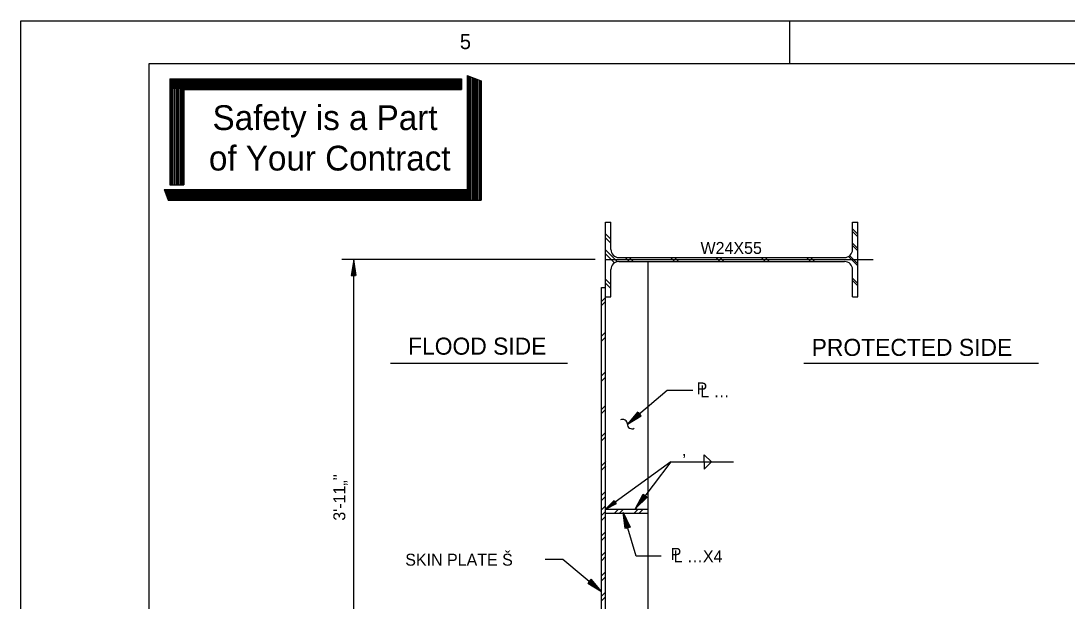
# Model space of a CAD drawing. Extents: x 4.9 to 31.6, y 3.9 to 22.6.
# Drawn here: x 4.91 to 13.07, y 18.06 to 22.59 of the extents above; entities that cross this region are included whole.
import ezdxf

# ---------------------------------------------------------------- set-up
doc = ezdxf.new("R2010")
doc.units = 0
for name, color, linetype in [('Level 1', 7, 'Continuous'), ('Level 10', 7, 'Continuous'), ('Level 2', 7, 'Continuous'), ('Level 25', 7, 'Continuous'), ('Level 3', 7, 'Continuous'), ('Level 44', 7, 'Continuous'), ('Level 50', 7, 'Continuous')]:
    doc.layers.add(name, color=color, linetype=linetype)

msp = doc.modelspace()

# ---------------------------------------------------------------- linework, layer by layer
at = {"layer": 'Level 1'}
for p, q in [((10.9069, 22.2594), (10.9069, 22.5927)), ((6.0674, 22.1412), (8.3454, 22.1412)), ((6.0674, 22.1412), (6.0674, 21.3139)), ((6.0674, 22.1306), (8.3454, 22.1306)), ((6.0674, 22.1206), (8.3454, 22.1206)), ((6.0781, 22.1412), (6.0781, 21.3139)), ((6.0881, 22.1412), (6.0881, 21.3139)), ((6.0988, 22.1412), (6.0988, 21.3139)), ((6.1088, 22.1412), (6.1088, 21.3139)), ((6.1194, 22.1412), (6.1194, 21.3139)), ((6.1301, 22.1412), (6.1301, 21.3139)), ((6.1401, 22.1412), (6.1401, 21.3139)), ((6.1508, 22.1412), (6.1508, 21.3139)), ((6.1614, 22.1412), (6.1614, 21.3139)), ((6.1714, 22.1412), (6.1714, 21.3139)), ((8.3454, 22.1412), (8.3454, 22.0579)), ((8.3874, 22.1659), (8.3874, 21.2766)), ((8.3874, 22.1659), (8.4988, 22.1246)), ((8.3948, 22.1632), (8.3948, 21.1932)), ((8.4048, 22.1592), (8.4048, 21.1932)), ((8.4154, 22.1552), (8.4154, 21.1932)), ((8.4261, 22.1512), (8.4261, 21.1932)), ((8.4361, 22.1479), (8.4361, 21.1932)), ((8.4468, 22.1439), (8.4468, 21.1932)), ((8.4568, 22.1399), (8.4568, 21.1932)), ((8.4674, 22.1359), (8.4674, 21.1932)), ((8.4781, 22.1326), (8.4781, 21.1932)), ((8.4881, 22.1246), (8.4881, 21.1932)), ((8.4988, 22.1246), (8.4988, 21.1932)), ((6.0674, 22.1099), (8.3454, 22.1099)), ((6.0674, 22.0992), (8.3454, 22.0992)), ((6.0674, 22.0892), (8.3454, 22.0892)), ((6.0674, 22.0786), (8.3454, 22.0786)), ((6.0674, 22.0686), (8.3454, 22.0686)), ((6.1788, 22.0579), (8.3454, 22.0579)), ((6.1788, 22.0579), (6.1788, 21.3139)), ((6.0674, 21.3139), (6.1788, 21.3139)), ((6.0254, 21.2766), (8.3874, 21.2766)), ((6.0254, 21.2766), (6.0561, 21.1932)), ((6.0294, 21.2659), (8.3948, 21.2659)), ((6.0328, 21.2559), (8.3948, 21.2559)), ((6.0368, 21.2452), (8.3948, 21.2452)), ((6.0408, 21.2346), (8.3948, 21.2346)), ((6.0448, 21.2246), (8.3948, 21.2246)), ((6.0488, 21.2139), (8.3948, 21.2139)), ((6.0521, 21.2039), (8.3948, 21.2039)), ((6.0561, 21.1932), (8.4988, 21.1932))]:
    msp.add_line(p, q, dxfattribs=at)
for points in [[(4.9069, 22.5927), (31.5735, 22.5927), (31.5735, 3.926), (4.9069, 3.926)], [(5.9069, 22.2594), (31.2402, 22.2594), (31.2402, 4.2594), (5.9069, 4.2594)]]:
    msp.add_lwpolyline(points, close=True, dxfattribs=at)
at = {"layer": 'Level 10'}
for p, q in [((9.4366, 20.4023), (9.4679, 20.4335)), ((9.4366, 20.3708), (9.4679, 20.402)), ((9.4366, 20.131), (9.4679, 20.1622)), ((9.4366, 20.0934), (9.4679, 20.1246)), ((9.4366, 19.8209), (9.4679, 19.8521)), ((9.4366, 19.781), (9.4679, 19.8122)), ((9.4366, 19.5606), (9.4679, 19.5918)), ((9.4366, 19.5279), (9.4679, 19.5591)), ((9.4353, 19.3159), (9.4666, 19.3472)), ((9.4366, 19.3486), (9.4679, 19.3799)), ((9.4379, 19.1234), (9.4692, 19.1546)), ((9.4379, 19.0895), (9.4692, 19.1207)), ((9.4366, 18.8873), (9.4679, 18.9185)), ((9.4366, 18.8496), (9.4679, 18.8808)), ((9.4366, 18.7754), (9.4679, 18.8067)), ((9.537, 18.7509), (9.5682, 18.7821)), ((9.5764, 18.7509), (9.6077, 18.7821)), ((9.6907, 18.7509), (9.7219, 18.7821)), ((9.7301, 18.7509), (9.7614, 18.7821)), ((9.4366, 18.7317), (9.4679, 18.7629)), ((9.4366, 18.6922), (9.4679, 18.7235)), ((9.4366, 18.6922), (9.4679, 18.7235)), ((9.4366, 18.5744), (9.4679, 18.6056)), ((9.4366, 18.5367), (9.4679, 18.5679)), ((9.4366, 18.4171), (9.4679, 18.4483)), ((9.4366, 18.3793), (9.4679, 18.4106)), ((9.4366, 18.2597), (9.4679, 18.291)), ((9.4366, 18.222), (9.4679, 18.2533)), ((9.4366, 18.1024), (9.4679, 18.1337)), ((9.4366, 18.0647), (9.4679, 18.0959))]:
    msp.add_line(p, q, dxfattribs=at)
at = {"layer": 'Level 2'}
for p, q in [((9.4679, 20.4384), (9.4679, 21.0217)), ((9.4679, 21.0217), (9.5095, 21.0217)), ((9.5095, 20.8082), (9.5095, 21.0217)), ((11.3949, 20.8082), (11.3949, 21.0217)), ((11.3949, 21.0217), (11.4366, 21.0217)), ((11.4366, 20.4384), (11.4366, 21.0217)), ((11.4366, 20.9272), (11.3949, 20.9688)), ((11.4366, 20.9083), (11.3949, 20.95)), ((11.4366, 20.8173), (11.3949, 20.8589)), ((11.4366, 20.7984), (11.3949, 20.8401)), ((9.572, 20.7457), (11.3324, 20.7457)), ((11.4366, 20.6806), (11.3672, 20.75)), ((9.4679, 20.73), (11.5564, 20.73)), ((9.5095, 20.4384), (9.5095, 20.6519)), ((9.572, 20.7144), (11.3324, 20.7144)), ((9.8012, 16.8271), (9.8012, 20.7144)), ((10.3429, 20.7144), (10.6762, 20.7144)), ((11.3949, 20.4384), (11.3949, 20.6519)), ((11.4366, 20.5438), (11.3949, 20.5855)), ((9.4366, 20.5113), (9.4679, 20.5113)), ((9.4366, 16.8271), (9.4366, 20.5113)), ((9.4679, 20.48), (9.4679, 20.5113)), ((9.4679, 16.8271), (9.4679, 20.5113)), ((11.4366, 20.525), (11.3949, 20.5667)), ((9.4679, 20.4384), (9.5095, 20.4384)), ((11.3949, 20.4384), (11.4366, 20.4384)), ((9.4679, 18.7509), (9.4679, 18.7821)), ((9.8012, 18.7509), (9.8012, 18.7821))]:
    msp.add_line(p, q, dxfattribs=at)
at = {"layer": 'Level 25'}
for p, q in [((9.5095, 20.8878), (9.4679, 20.9295)), ((9.5095, 20.8565), (9.4679, 20.8981)), ((9.5604, 20.7133), (9.4659, 20.8078)), ((9.538, 20.7044), (9.4659, 20.7765)), ((9.6516, 20.7144), (9.6203, 20.7457)), ((9.683, 20.7144), (9.6517, 20.7457)), ((10.0051, 20.7144), (9.9739, 20.7457)), ((10.0365, 20.7144), (10.0053, 20.7457)), ((10.3587, 20.7144), (10.3274, 20.7457)), ((10.3901, 20.7144), (10.3588, 20.7457)), ((10.7123, 20.7144), (10.681, 20.7457)), ((10.7436, 20.7144), (10.7124, 20.7457)), ((11.0658, 20.7144), (11.0346, 20.7457)), ((11.0972, 20.7144), (11.0659, 20.7457)), ((11.4366, 20.6972), (11.374, 20.7597)), ((7.503, 16.803), (7.503, 20.73)), ((9.5095, 20.5343), (9.4679, 20.576)), ((9.5095, 20.5029), (9.4679, 20.5446)), ((9.1716, 19.9197), (7.7908, 19.9197)), ((12.8447, 19.9197), (11.0146, 19.9197)), ((10.2386, 19.2061), (10.2945, 19.1502)), ((10.2386, 19.1498), (10.2386, 19.2061)), ((9.9777, 19.1504), (9.4679, 18.7821)), ((9.9777, 19.1504), (10.4673, 19.1504)), ((10.2386, 19.151), (10.2386, 19.0948)), ((10.2386, 19.0948), (10.2945, 19.1506)), ((9.4679, 18.7821), (9.4679, 18.7821)), ((9.4889, 18.7974), (9.4889, 18.7974))]:
    msp.add_line(p, q, dxfattribs=at)
msp.add_lwpolyline([(9.5346, 18.8494), (9.4679, 18.7821), (9.5527, 18.8243), (9.5372, 18.8458), (9.4889, 18.7974), (9.5466, 18.826), (9.5366, 18.8398), (9.5092, 18.812), (9.5404, 18.8277), (9.5363, 18.8334), (9.5303, 18.8272)], dxfattribs=at)
for centre, start, end in [((9.572, 20.8082), 180, 270), ((11.3324, 20.8082), 270, 0), ((9.572, 20.6519), 90, 180), ((11.3324, 20.6519), 0, 90)]:
    msp.add_arc(centre, 0.0625, start, end, dxfattribs=at)
at = {"layer": 'Level 3'}
for p, q in [((10.4866, 20.7297), (10.4866, 20.7297)), ((10.5743, 20.7136), (10.5743, 20.7136)), ((9.9777, 19.1504), (9.7017, 18.7875))]:
    msp.add_line(p, q, dxfattribs=at)
for points in [[(10.5747, 20.7144), (10.5743, 20.7136)], [(10.5746, 20.7144), (10.5743, 20.7136), (10.5749, 20.7144)], [(10.1495, 19.7071), (9.9488, 19.7071), (9.638, 19.4453)], [(9.9018, 18.4156), (9.7058, 18.4156), (9.6058, 18.7552)], [(8.9967, 18.392), (9.1355, 18.392), (9.4376, 18.1395)]]:
    msp.add_lwpolyline(points, dxfattribs=at)
at = {"layer": 'Level 44'}
for p, q in [((9.4679, 18.7821), (9.8012, 18.7821)), ((9.4679, 18.7509), (9.8012, 18.7509))]:
    msp.add_line(p, q, dxfattribs=at)
for centre, start, end in [((9.6012, 19.4456), 359.59813, 117.47734), ((9.6748, 19.4451), 179.59813, 297.47734)]:
    msp.add_arc(centre, 0.0368, start, end, dxfattribs=at)
at = {"layer": 'Level 50'}
for p, q in [((9.3868, 20.73), (7.4105, 20.73)), ((7.503, 20.73), (7.503, 20.73)), ((7.503, 20.6954), (7.503, 20.6954)), ((9.638, 19.4453), (9.638, 19.4453)), ((9.6645, 19.4676), (9.6645, 19.4676)), ((9.7017, 18.7875), (9.7017, 18.7875)), ((9.7227, 18.8151), (9.7227, 18.8151)), ((9.6058, 18.7552), (9.6058, 18.7552)), ((9.6156, 18.7219), (9.6156, 18.7219)), ((9.411, 18.1617), (9.411, 18.1617)), ((9.4376, 18.1395), (9.4376, 18.1395))]:
    msp.add_line(p, q, dxfattribs=at)
for points in [[(7.5236, 20.6054), (7.503, 20.73), (7.4823, 20.6054), (7.5176, 20.6054), (7.503, 20.6954), (7.489, 20.6107), (7.5116, 20.6107), (7.503, 20.662), (7.4956, 20.616), (7.505, 20.616), (7.503, 20.6274)], [(9.72, 19.5414), (9.638, 19.4453), (9.7467, 19.5098), (9.7239, 19.5368), (9.6645, 19.4676), (9.7383, 19.5115), (9.7237, 19.5288), (9.69, 19.4891), (9.7299, 19.5131), (9.7239, 19.5203), (9.7165, 19.5114)], [(9.7936, 18.8742), (9.7017, 18.7875), (9.7607, 18.8993), (9.7888, 18.8779), (9.7227, 18.8151), (9.7628, 18.891), (9.7808, 18.8773), (9.7428, 18.8416), (9.7648, 18.8827), (9.7723, 18.8771), (9.7638, 18.8692)], [(9.6212, 18.6298), (9.6058, 18.7552), (9.6609, 18.6414), (9.627, 18.6315), (9.6156, 18.7219), (9.6529, 18.6447), (9.6312, 18.6383), (9.625, 18.69), (9.645, 18.6479), (9.6361, 18.6453), (9.6348, 18.6567)], [(9.3287, 18.2036), (9.4376, 18.1395), (9.3552, 18.2353), (9.3326, 18.2082), (9.411, 18.1617), (9.355, 18.2267), (9.3405, 18.2094), (9.3854, 18.1831), (9.3548, 18.2182), (9.3489, 18.211), (9.3588, 18.2053)]]:
    msp.add_lwpolyline(points, dxfattribs=at)

# ---------------------------------------------------------------- texts
at = {"layer": 'Level 1'}
for s, height, p in [('5', 0.1168, (8.3314, 22.3726)), ('Safety is a Part', 0.193584, (6.4018, 21.7407)), ('of Your Contract', 0.193584, (6.3737, 21.4248))]:
    msp.add_text(s, height=height, dxfattribs=at).set_placement(p)
at = {"layer": 'Level 25'}
for s, height, p in [('W24X55', 0.09329, (10.209, 20.7738)), ('FLOOD SIDE', 0.13329, (7.9273, 19.9873)), ('PROTECTED SIDE', 0.133292, (11.0759, 19.9776)), ('P', 0.0933, (10.1781, 19.677)), ('L …', 0.09329, (10.2072, 19.6542)), ('‚', 0.0933, (10.0677, 19.1988)), ('SKIN PLATE Š', 0.093292, (7.9054, 18.3402)), ('P', 0.0933, (9.9761, 18.3857)), ('L …X4', 0.09329, (9.999, 18.3668))]:
    msp.add_text(s, height=height, dxfattribs=at).set_placement(p)
msp.add_text("3'-11„''", height=0.09329, rotation=90, dxfattribs=at).set_placement((7.4378, 18.6913))

doc.saveas('drawing.dxf')
